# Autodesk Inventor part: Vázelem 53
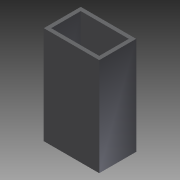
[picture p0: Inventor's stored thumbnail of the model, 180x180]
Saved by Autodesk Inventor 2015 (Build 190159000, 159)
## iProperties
Created: 2013-02
Part Number: Vázelem 53
Material: Generic
Document SubType Name: Modeling
Designer: Marci
Density: 1 g/cm^3
Appearance: Gray
Author: Marci
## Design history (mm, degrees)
sketch "Sketch1"
  geometry: L1 (0, 10)-(15, 10); L2 (15, 10)-(15, -10); L3 (15, -10)-(-15, -10); L4 (-15, -10)-(-15, 10); L5 (-15, 10)-(0, 10); L6 (0, 8)-(13, 8); L7 (13, 8)-(13, -8); L8 (13, -8)-(-13, -8); L9 (-13, -8)-(-13, 8); L10 (-13, 8)-(0, 8); 1 further point
  constraints: 20 end point, 2 collinear, 2 parallel, 4 other
  dimensions: "d0" = 10 distance of point (0, 0) L1.start; "d1" = 15 distance of L1.start L1.end; "d2" = 20 distance of L1.end L2.end; "d3" = 30 distance of L2.end L3.end; "d4" = 2 distance between parallel lines of L4 L9
extrude "Extrusion1" new body sketch "Sketch1" distance "d5" = 53; taper "d6" = 0 deg
body "Solid1"
